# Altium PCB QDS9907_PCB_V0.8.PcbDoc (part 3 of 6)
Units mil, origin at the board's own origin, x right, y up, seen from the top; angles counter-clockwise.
Board outline 3410.03 x 4010.03 mil, 8 copper layers (Top Layer, GND1, INT1, INT2, PWR1, GND2, GND3, Bottom Layer), stack 81.668 mil thick; 250 components, 129 nets, 7010 pads, 701 vias.
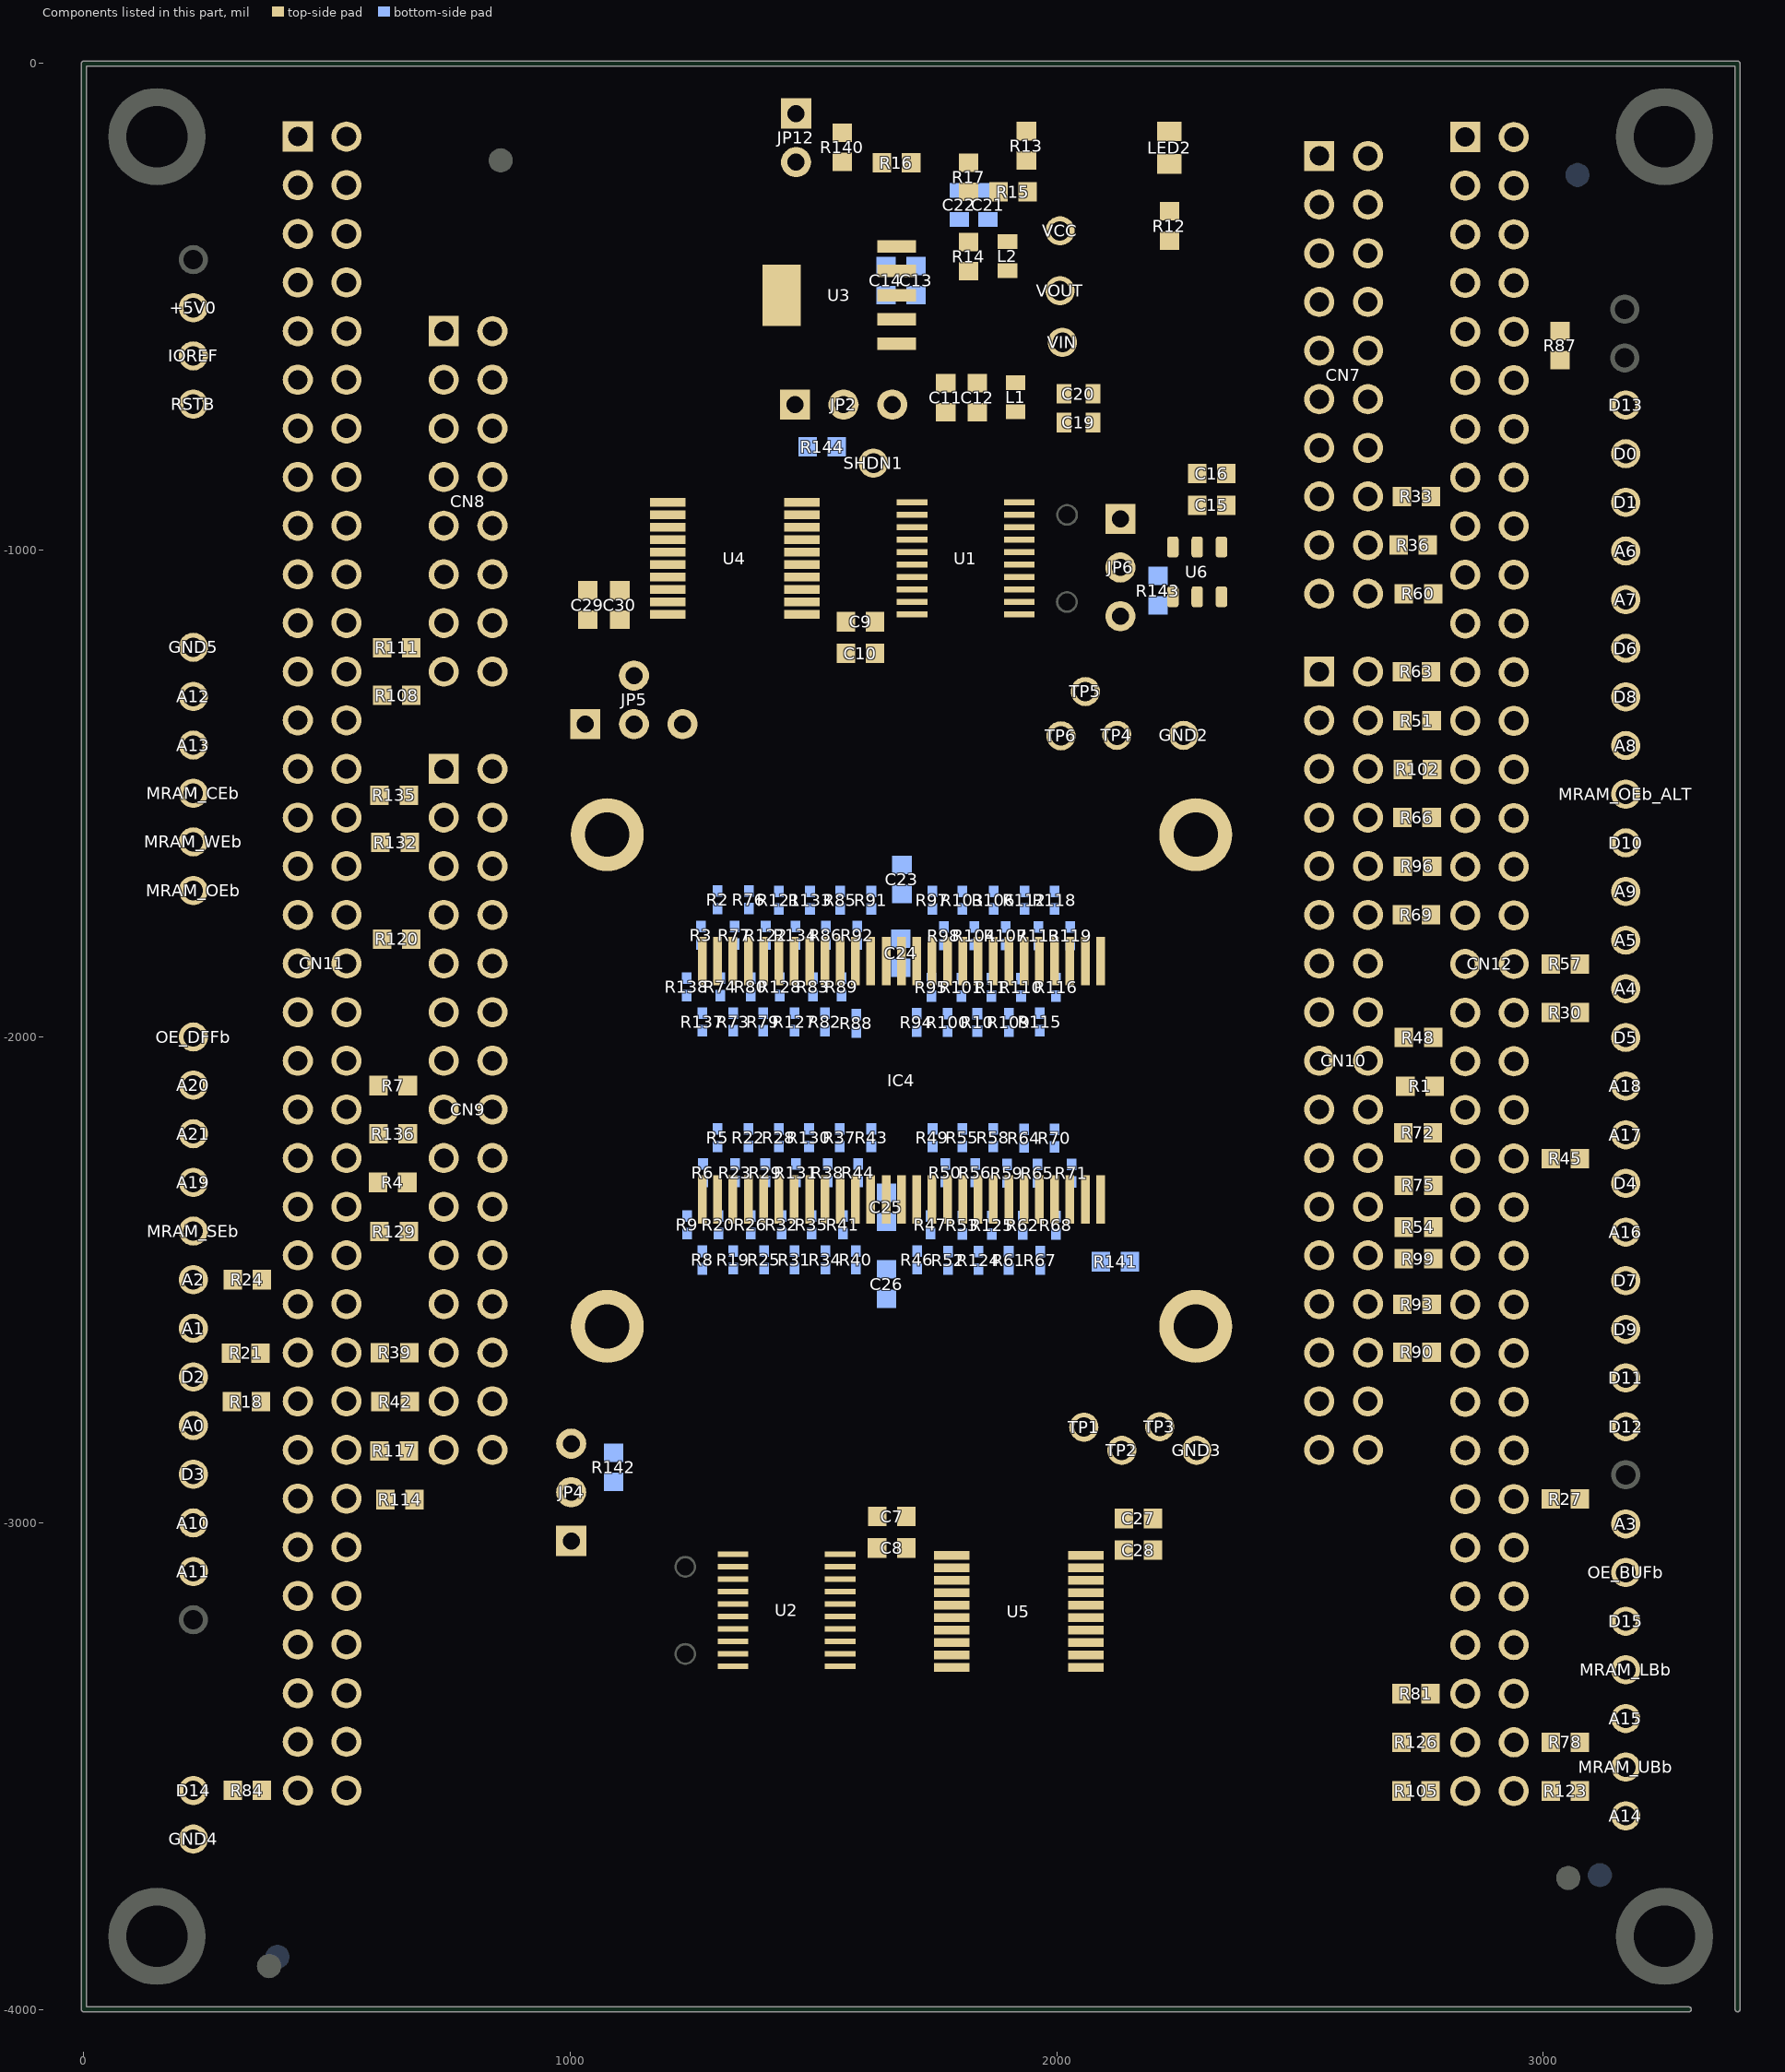
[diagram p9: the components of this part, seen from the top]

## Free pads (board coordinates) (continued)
  round 1.54 on Bottom Overlay: ""(1469.48,-3788.44) ""(1469.57,-3794.27) ""(1469.57,-3794.27) ""(1469.57,-3794.27) ""(1469.57,-3794.27) ""(1469.85,-3797.55) ""(1469.85,-3797.55) ""(1469.85,-3797.55) ""(1469.85,-3797.55) ""(1469.99,-3768.89) ""(1469.99,-3768.89) ""(1469.99,-3768.89) ""(1469.99,-3768.89) ""(1470.3,-3787.9) ""(1470.3,-3787.9) ""(1470.3,-3787.9) ""(1470.3,-3787.9) ""(1470.58,-3795.09) ""(1470.58,-3795.09) ""(1470.58,-3795.09) ""(1470.58,-3795.09) ""(1470.67,-3771.14) ""(1470.67,-3771.14) ""(1470.67,-3771.14) ""(1470.67,-3771.14) ""(1471.21,-3768.56) ""(1471.21,-3768.56) ""(1471.21,-3768.56) ""(1471.21,-3768.56) ""(1471.49,-3770.86) ""(1471.49,-3770.86) ""(1471.49,-3770.86) ""(1471.49,-3770.86) ""(1471.58,-3779.24) ""(1471.58,-3779.24) ""(1471.58,-3779.24) ""(1471.58,-3779.24) ""(1471.67,-3786.99) ""(1471.67,-3786.99) ""(1471.67,-3786.99) ""(1471.67,-3786.99) ""(1471.85,-3795.46) ""(1471.85,-3795.46) ""(1471.85,-3795.46) ""(1471.85,-3795.46) ""(1472.58,-3797.91) ""(1472.58,-3797.91) ""(1472.58,-3797.91) ""(1472.58,-3797.91) ""(1473.22,-3770.5) ""(1473.22,-3770.5) ""(1473.22,-3770.5) ""(1473.22,-3770.5) ""(1473.31,-3795.73) ""(1473.31,-3795.73) ""(1473.31,-3795.73) ""(1473.31,-3795.73) ""(1473.4,-3786.44) ""(1473.4,-3786.44) ""(1473.4,-3786.44) ""(1473.4,-3786.44) ""(1473.95,-3778.06) ""(1473.95,-3778.06) ""(1473.95,-3778.06) ""(1473.95,-3778.06) ""(1474.33,-3795.67) ""(1474.33,-3795.67) ""(1474.33,-3795.67) ""(1474.33,-3795.67) ""(1474.4,-3768.28) ""(1474.4,-3768.28) ""(1474.4,-3768.28) ""(1474.4,-3768.28) ""(1474.5,-3798.01) ""(1474.5,-3798.01) ""(1474.5,-3798.01) ""(1474.5,-3798.01) ""(1474.77,-3770.77) ""(1474.77,-3770.77) ""(1474.77,-3770.77) ""(1474.77,-3770.77) ""(1475.14,-3795.56) ""(1475.14,-3795.56) ""(1475.14,-3795.56) ""(1475.14,-3795.56) ""(1475.33,-3797.89) ""(1475.33,-3797.89) ""(1475.33,-3797.89) ""(1475.33,-3797.89) ""(1475.68,-3777.15) ""(1475.68,-3777.15) ""(1475.68,-3777.15) ""(1475.68,-3777.15) ""(1475.77,-3785.25) ""(1475.77,-3785.25) ""(1475.77,-3785.25) ""(1475.77,-3785.25) ""(1475.85,-3768.48) ""(1475.85,-3768.48) ""(1475.85,-3768.48) ""(1475.85,-3768.48) ""(1475.96,-3771.23) ""(1475.96,-3771.23) ""(1475.96,-3771.23) ""(1475.96,-3771.23) ""(1475.96,-3797.8) ""(1475.96,-3797.8) ""(1475.96,-3797.8) ""(1475.96,-3797.8) ""(1476.03,-3795.43) ""(1476.03,-3795.43) ""(1476.03,-3795.43) ""(1476.03,-3795.43) ""(1476.69,-3776.15) ""(1476.69,-3776.15) ""(1476.69,-3776.15) ""(1476.69,-3776.15) ""(1476.7,-3795.28) ""(1476.7,-3795.28) ""(1476.7,-3795.28) ""(1476.7,-3795.28) ""(1476.78,-3772.41) ""(1476.78,-3772.41) ""(1476.78,-3772.41) ""(1476.78,-3772.41) ""(1476.83,-3797.65) ""(1476.83,-3797.65) ""(1476.83,-3797.65) ""(1476.83,-3797.65) ""(1477.23,-3768.89) ""(1477.23,-3768.89) ""(1477.23,-3768.89) ""(1477.23,-3768.89) ""(1477.23,-3774.87) ""(1477.23,-3774.87) ""(1477.23,-3774.87) ""(1477.23,-3774.87) ""(1477.23,-3773.78) ""(1477.23,-3773.78) ""(1477.23,-3773.78) ""(1477.23,-3773.78) ""(1477.33,-3797.56) ""(1477.33,-3797.56) ""(1477.33,-3797.56) ""(1477.33,-3797.56) ""(1477.51,-3784.62) ""(1477.51,-3784.62) ""(1477.51,-3784.62) ""(1477.51,-3784.62) ""(1477.87,-3797.37) ""(1477.87,-3797.37) ""(1477.87,-3797.37) ""(1477.87,-3797.37) ""(1478.01,-3794.58) ""(1478.01,-3794.58) ""(1478.01,-3794.58) ""(1478.01,-3794.58) ""(1478.44,-3794.21) ""(1478.44,-3794.21) ""(1478.44,-3794.21) ""(1478.44,-3794.21) ""(1478.6,-3769.58) ""(1478.6,-3769.58) ""(1478.6,-3769.58) ""(1478.6,-3769.58) ""(1478.96,-3793.73) ""(1478.96,-3793.73) ""(1478.96,-3793.73) ""(1478.96,-3793.73) ""(1479.15,-3796.64) ""(1479.15,-3796.64) ""(1479.15,-3796.64) ""(1479.15,-3796.64) ""(1479.33,-3783.34) ""(1479.33,-3783.34) ""(1479.33,-3783.34) ""(1479.33,-3783.34) ""(1479.53,-3796.39) ""(1479.53,-3796.39) ""(1479.53,-3796.39) ""(1479.53,-3796.39) ""(1479.6,-3792.72) ""(1479.6,-3792.72) ""(1479.79,-3796.28) ""(1479.79,-3796.28) ""(1479.79,-3796.28) ""(1479.79,-3796.28) ""(1480.05,-3796.28) ""(1480.05,-3796.28) ""(1480.05,-3796.28) ""(1480.05,-3796.28) ""(1480.06,-3770.59) ""(1480.06,-3770.59) ""(1480.06,-3770.59) ""(1480.06,-3770.59) ""(1480.33,-3791.36) ""(1480.33,-3791.36) ""(1480.33,-3791.36) ""(1480.33,-3791.36) ""(1480.36,-3796.34) ""(1480.36,-3796.34) ""(1480.36,-3796.34) ""(1480.36,-3796.34) ""(1480.44,-3796.37) ""(1480.44,-3796.37) ""(1480.57,-3790.47) ""(1480.57,-3790.47) ""(1480.57,-3790.47) ""(1480.58,-3790.47) ""(1480.58,-3790.47) ""(1480.79,-3782.25) ""(1480.79,-3782.25) ""(1480.79,-3782.25) ""(1480.79,-3782.25) ""(1480.87,-3796.75) ""(1480.87,-3796.75) ""(1480.87,-3796.75) ""(1480.87,-3796.75) ""(1481.32,-3789.9) ""(1481.32,-3789.9) ""(1481.32,-3789.9) ""(1481.32,-3789.9) ""(1481.32,-3789.9) ""(1481.48,-3797.16) ""(1481.48,-3797.16) ""(1481.48,-3797.16) ""(1481.52,-3772.05) ""(1481.52,-3772.05) ""(1481.52,-3772.05) ""(1481.52,-3772.05) ""(1481.7,-3797.19) ""(1481.7,-3797.19) ""(1481.7,-3797.19) ""(1481.7,-3797.19) ""(1481.7,-3789.9) ""(1481.7,-3789.9) ""(1481.7,-3789.9) ""(1481.7,-3789.9) ""(1481.97,-3781.06) ""(1481.97,-3781.06) ""(1481.97,-3781.06) ""(1481.97,-3781.06) ""(1482.34,-3773.41) ""(1482.34,-3773.41) ""(1482.34,-3773.41) ""(1482.34,-3773.41) ""(1482.79,-3779.61) ""(1482.79,-3779.61) ""(1482.79,-3779.61) ""(1482.79,-3779.61) ""(1482.98,-3777.06) ""(1482.98,-3777.06) ""(1482.98,-3775.23) ""(1482.98,-3775.23) ""(1482.98,-3777.06) ""(1482.98,-3777.06) ""(1482.98,-3775.23) ""(1482.98,-3775.23) ""(1483.25,-3796.42) ""(1483.25,-3796.42) ""(1483.25,-3796.42) ""(1483.25,-3790.67) ""(1483.25,-3790.67) ""(1483.25,-3790.67) ""(1483.25,-3796.42) ""(1483.25,-3796.42) ""(1483.25,-3790.67) ""(1483.25,-3790.67) ""(1493.57,-3796.37) ""(1493.57,-3796.37) ""(1493.57,-3796.37) ""(1493.57,-3796.37) ""(1493.57,-3796.07) ""(1493.57,-3796.07) ""(1493.57,-3796.07) ""(1493.57,-3796.07) ""(1494.1,-3795.33) ""(1494.1,-3795.33) ""(1494.1,-3795.33) ""(1494.1,-3795.33) ""(1494.34,-3797.14) ""(1494.34,-3797.14) ""(1494.34,-3797.14) ""(1494.34,-3797.14) ""(1494.54,-3795.19) ""(1494.54,-3795.19) ""(1494.54,-3795.19) ""(1494.54,-3795.19) ""(1495.13,-3795.06) ""(1495.13,-3795.06) ""(1495.13,-3795.06) ""(1495.13,-3795.06) ""(1495.43,-3794.76) ""(1495.43,-3794.76) ""(1495.43,-3794.76) ""(1495.43,-3794.76) ""(1495.64,-3794.51) ""(1495.64,-3794.51) ""(1495.64,-3794.51) ""(1495.64,-3794.51) ""(1495.89,-3794.04) ""(1495.89,-3794.04) ""(1495.89,-3794.04) ""(1495.89,-3794.04) ""(1496.02,-3793.54) ""(1496.02,-3793.54) ""(1496.02,-3793.54) ""(1496.02,-3793.54) ""(1496.02,-3781.4) ""(1496.02,-3781.4) ""(1496.02,-3781.4) ""(1496.02,-3781.4) ""(1496.04,-3780.85) ""(1496.04,-3780.85) ""(1496.04,-3780.85) ""(1496.04,-3780.85) ""(1496.15,-3780.46) ""(1496.15,-3780.46) ""(1496.15,-3780.46) ""(1496.15,-3780.46) ""(1496.59,-3779.39) ""(1496.59,-3779.39) ""(1496.59,-3779.39) ""(1496.59,-3779.39) ""(1497.05,-3778.59) ""(1497.05,-3778.59) ""(1497.05,-3778.59) ""(1497.05,-3778.59) ""(1497.49,-3778.12) ""(1497.49,-3778.12) ""(1497.49,-3778.12) ""(1497.49,-3778.12) ""(1498.67,-3777.46) ""(1498.67,-3777.46) ""(1498.67,-3777.46) ""(1498.67,-3777.46) ""(1500.31,-3776.96) ""(1500.31,-3776.96) ""(1500.32,-3776.96) ""(1500.32,-3776.96) ""(1501.96,-3776.96) ""(1501.96,-3776.96) ""(1501.96,-3776.96) ""(1501.96,-3776.96) ""(1502,-3793.83) ""(1502,-3793.83) ""(1502.04,-3794.38) ""(1502.04,-3794.38) ""(1502.04,-3782.23) ""(1502.04,-3782.23) ""(1502.04,-3794.38) ""(1502.04,-3794.38) ""(1502.04,-3782.23) ""(1502.04,-3782.23) ""(1502.21,-3794.64) ""(1502.21,-3794.64) ""(1502.21,-3794.64) ""(1502.21,-3794.64) ""(1502.21,-3781.72) ""(1502.21,-3781.72) ""(1502.21,-3781.72) ""(1502.21,-3781.72) ""(1502.25,-3797.14) ""(1502.25,-3797.14) ""(1502.25,-3797.14) ""(1502.25,-3797.14) ""(1502.42,-3781.38) ""(1502.42,-3781.38) ""(1502.42,-3781.38) ""(1502.42,-3781.38) ""(1502.51,-3794.98) ""(1502.51,-3794.98) ""(1502.51,-3794.98) ""(1502.51,-3794.98) ""(1502.68,-3795.06) ""(1502.68,-3795.06) ""(1502.68,-3795.06) ""(1502.68,-3795.06) ""(1502.76,-3780.87) ""(1502.76,-3780.87) ""(1502.76,-3780.87) ""(1502.76,-3780.87) ""(1503.21,-3797.14) ""(1503.21,-3797.14) ""(1503.21,-3797.14) ""(1503.21,-3797.14) ""(1503.21,-3795.06) ""(1503.21,-3795.06) ""(1503.21,-3795.06) ""(1503.21,-3795.06) ""(1503.31,-3780.49) ""(1503.31,-3780.49) ""(1503.31,-3780.49) ""(1503.31,-3780.49) ""(1503.91,-3777.19) ""(1503.91,-3777.19) ""(1503.91,-3777.19) ""(1503.91,-3777.19) ""(1503.95,-3780.15) ""(1503.95,-3780.15) ""(1503.95,-3780.15) ""(1503.95,-3780.15) ""(1503.98,-3796.37) ""(1503.98,-3796.37) ""(1503.98,-3796.37) ""(1503.98,-3796.37) ""(1503.98,-3795.83) ""(1503.98,-3795.83) ""(1503.98,-3795.83) ""(1503.98,-3795.83) ""(1504.55,-3777.28) ""(1504.55,-3777.28) ""(1504.55,-3777.28) ""(1504.55,-3777.28) ""(1504.76,-3779.97) ""(1504.76,-3779.97) ""(1504.76,-3779.97) ""(1504.76,-3779.97) ""(1505.24,-3780.02) ""(1505.24,-3780.02) ""(1505.24,-3780.02) ""(1505.24,-3780.02) ""(1505.34,-3777.5) ""(1505.34,-3777.5) ""(1505.34,-3777.5) ""(1505.34,-3777.5) ""(1505.52,-3796.41) ""(1505.52,-3796.41) ""(1505.52,-3796.41) ""(1505.52,-3796.41) ""(1505.52,-3796.02) ""(1505.52,-3796.02) ""(1505.52,-3796.02) ""(1505.52,-3796.02) ""(1505.54,-3780.06) ""(1505.54,-3780.06) ""(1505.54,-3780.06) ""(1505.54,-3780.06) ""(1505.88,-3780.2) ""(1505.88,-3780.2) ""(1505.88,-3780.2) ""(1505.88,-3780.2) ""(1505.98,-3777.81) ""(1505.98,-3777.81) ""(1505.98,-3777.81) ""(1505.98,-3777.81) ""(1506.13,-3780.37) ""(1506.13,-3780.37) ""(1506.13,-3780.37) ""(1506.13,-3780.37) ""(1506.21,-3795.25) ""(1506.21,-3795.25) ""(1506.21,-3795.25) ""(1506.21,-3795.25) ""(1506.29,-3797.18) ""(1506.41,-3780.56) ""(1506.41,-3780.56) ""(1506.41,-3780.56) ""(1506.41,-3780.56) ""(1506.56,-3778.19) ""(1506.56,-3778.19) ""(1506.56,-3778.19) ""(1506.56,-3778.19) ""(1506.68,-3780.62) ""(1506.68,-3780.62) ""(1506.68,-3780.62) ""(1506.68,-3780.62) ""(1506.83,-3795.19) ""(1506.83,-3795.19) ""(1506.83,-3795.19) ""(1506.83,-3795.19) ""(1506.94,-3780.54) ""(1506.94,-3780.54) ""(1506.94,-3780.54) ""(1506.94,-3780.54) ""(1507.04,-3778.52) ""(1507.04,-3778.52) ""(1507.04,-3778.52) ""(1507.04,-3778.52) ""(1507.21,-3795.1) ""(1507.21,-3795.1) ""(1507.21,-3795.1) ""(1507.21,-3795.1) ""(1507.3,-3778.87) ""(1507.3,-3778.87) ""(1507.3,-3778.87) ""(1507.3,-3778.87) ""(1507.33,-3780.58) ""(1507.33,-3780.58) ""(1507.33,-3780.58) ""(1507.33,-3780.58) ""(1507.42,-3794.89) ""(1507.42,-3794.89) ""(1507.42,-3794.89) ""(1507.42,-3794.89) ""(1507.55,-3779.26) ""(1507.55,-3779.26) ""(1507.55,-3779.26) ""(1507.55,-3779.26) ""(1507.58,-3780.79) ""(1507.58,-3780.79) ""(1507.58,-3780.79) ""(1507.58,-3780.79) ""(1507.63,-3779.33) ""(1507.63,-3779.33) ""(1507.63,-3779.33) ""(1507.63,-3779.33) ""(1507.68,-3794.6) ""(1507.68,-3794.6) ""(1507.68,-3794.6) ""(1507.68,-3794.6) ""(1507.79,-3781.11) ""(1507.79,-3781.11) ""(1507.79,-3781.11) ""(1507.79,-3781.11) ""(1507.8,-3779.42) ""(1507.8,-3779.42) ""(1507.8,-3779.42) ""(1507.8,-3779.42) ""(1507.81,-3794.17) ""(1507.81,-3794.17) ""(1507.81,-3794.17) ""(1507.81,-3794.17) ""(1507.89,-3793.62) ""(1507.89,-3793.62) ""(1507.89,-3782.74) ""(1507.89,-3782.74) ""(1507.89,-3781.42) ""(1507.89,-3781.42) ""(1507.89,-3793.62) ""(1507.89,-3793.62) ""(1507.89,-3782.74) ""(1507.89,-3782.74) ""(1507.89,-3781.42) ""(1507.89,-3781.42) ""(1507.92,-3779.47) ""(1507.92,-3779.47) ""(1507.92,-3779.47) ""(1507.92,-3779.47) ""(1508.03,-3779.48) ""(1508.03,-3779.48) ""(1508.03,-3779.48) ""(1508.03,-3779.48) ""(1508.15,-3779.46) ""(1508.15,-3779.46) ""(1508.15,-3779.46) ""(1508.15,-3779.46) ""(1508.26,-3779.27) ""(1508.26,-3779.27) ""(1508.26,-3779.27) ""(1508.26,-3779.27) ""(1508.28,-3779.18) ""(1508.28,-3779.18) ""(1508.28,-3779.18) ""(1508.28,-3779.18) ""(1508.28,-3778.38) ""(1508.28,-3778.38) ""(1508.28,-3778.38) ""(1508.28,-3778.38) ""(1509.05,-3777.61) ""(1509.05,-3777.61) ""(1509.05,-3777.61) ""(1509.05,-3777.61) ""(1514.04,-3793.11) ""(1514.04,-3793.11) ""(1514.04,-3793.11) ""(1514.04,-3793.11) ""(1514.04,-3781.34) ""(1514.04,-3781.34) ""(1514.04,-3781.34) ""(1514.04,-3781.34) ""(1514.12,-3780.91) ""(1514.12,-3780.91) ""(1514.16,-3794.09) ""(1514.16,-3794.09) ""(1514.33,-3794.43) ""(1514.33,-3794.43) ""(1514.33,-3794.43) ""(1514.33,-3794.43) ""(1514.38,-3780.53) ""(1514.38,-3780.53) ""(1514.38,-3780.53) ""(1514.38,-3780.53) ""(1514.72,-3794.76) ""(1514.72,-3794.76) ""(1514.72,-3794.76) ""(1514.72,-3794.76) ""(1514.76,-3780.24) ""(1514.76,-3780.24) ""(1514.76,-3780.24) ""(1514.76,-3780.24) ""(1515.14,-3780.07) ""(1515.14,-3780.07) ""(1515.14,-3780.07) ""(1515.14,-3780.07) ""(1515.18,-3795.1) ""(1515.18,-3795.1) ""(1515.18,-3795.1) ""(1515.18,-3795.1) ""(1515.43,-3797.18) ""(1515.43,-3797.18) ""(1515.43,-3797.18) ""(1515.43,-3797.18) ""(1515.65,-3779.98) ""(1515.65,-3779.98) ""(1515.65,-3779.98) ""(1515.65,-3779.98) ""(1515.69,-3795.29) ""(1515.69,-3795.29) ""(1515.69,-3795.29) ""(1515.69,-3795.29) ""(1515.99,-3779.9) ""(1515.99,-3779.9) ""(1515.99,-3779.9) ""(1515.99,-3779.9) ""(1516.11,-3777.7) ""(1516.11,-3777.7) ""(1516.11,-3777.7) ""(1516.11,-3777.7) ""(1516.16,-3779.73) ""(1516.16,-3779.73) ""(1516.16,-3779.73) ""(1516.16,-3779.73) ""(1516.2,-3796.41) ""(1516.2,-3796.41) ""(1516.2,-3796.41) ""(1516.2,-3796.41) ""(1516.2,-3796.01) ""(1516.2,-3796.01) ""(1516.2,-3796.01) ""(1516.2,-3796.01) ""(1516.24,-3779.39) ""(1516.24,-3779.39) ""(1516.24,-3779.39) ""(1516.24,-3779.39) ""(1516.24,-3777.95) ""(1516.24,-3777.95) ""(1516.24,-3777.95) ""(1516.24,-3777.95) ""(1519.62,-3777.67) ""(1519.62,-3777.67) ""(1519.62,-3777.67) ""(1519.62,-3777.67) ""(1519.76,-3775.94) ""(1519.76,-3775.94) ""(1519.76,-3775.94) ""(1519.76,-3775.94) ""(1520.03,-3798.98) ""(1520.03,-3798.98) ""(1520.03,-3775.45) ""(1520.03,-3775.45) ""(1520.03,-3798.98) ""(1520.03,-3798.98) ""(1520.03,-3775.45) ""(1520.03,-3775.45) ""(1520.17,-3800.36) ""(1520.17,-3800.36) ""(1520.17,-3800.36) ""(1520.17,-3800.36) ""(1520.24,-3778.98) ""(1520.24,-3778.98) ""(1520.24,-3778.98) ""(1520.24,-3778.98) ""(1520.38,-3797.25) ""(1520.38,-3797.25) ""(1520.38,-3797.25) ""(1520.38,-3797.25) ""(1520.59,-3779.19) ""(1520.59,-3779.19) ""(1520.59,-3779.19) ""(1520.59,-3779.19) ""(1520.66,-3774.9) ""(1520.66,-3774.9) ""(1520.66,-3774.9) ""(1520.66,-3774.9) ""(1520.73,-3801.88) ""(1520.73,-3801.88) ""(1520.73,-3801.88) ""(1520.73,-3801.88) ""(1520.93,-3796.35) ""(1520.93,-3796.35) ""(1520.93,-3796.35) ""(1520.93,-3796.35) ""(1521.21,-3779.33) ""(1521.21,-3779.33) ""(1521.21,-3774.49) ""(1521.21,-3774.49) ""(1521.21,-3779.33) ""(1521.21,-3779.33) ""(1521.21,-3774.49) ""(1521.21,-3774.49) ""(1521.42,-3785.21) ""(1521.42,-3785.21) ""(1521.42,-3785.21) ""(1521.42,-3785.21) ""(1521.56,-3783.62) ""(1521.56,-3783.62) ""(1521.56,-3783.62) ""(1521.56,-3783.62) ""(1521.63,-3786.8) ""(1521.63,-3786.8) ""(1521.63,-3786.8) ""(1521.63,-3786.8) ""(1521.76,-3782.23) ""(1521.76,-3782.23) ""(1521.76,-3782.23) ""(1521.76,-3782.23) ""(1521.9,-3779.33) ""(1521.9,-3779.33) ""(1521.9,-3779.33) ""(1521.9,-3779.33) ""(1521.9,-3774.21) ""(1521.9,-3774.21) ""(1521.9,-3774.21) ""(1521.9,-3774.21) ""(1521.97,-3803.4) ""(1521.97,-3803.4) ""(1521.97,-3803.4) ""(1521.97,-3803.4) ""(1522.25,-3795.1) ""(1522.25,-3795.1) ""(1522.25,-3795.1) ""(1522.25,-3795.1) ""(1522.25,-3788.46) ""(1522.25,-3788.46) ""(1522.25,-3788.46) ""(1522.25,-3788.46) ""(1522.39,-3779.33) ""(1522.39,-3779.33) ""(1522.39,-3779.33) ""(1522.39,-3779.33) ""(1522.46,-3780.99) ""(1522.46,-3780.99) ""(1522.46,-3780.99) ""(1522.46,-3780.99) ""(1522.73,-3779.12) ""(1522.73,-3779.12) ""(1522.73,-3779.12) ""(1522.73,-3779.12) ""(1522.87,-3778.64) ""(1522.87,-3778.64) ""(1522.87,-3778.64) ""(1522.87,-3778.64) ""(1522.87,-3778.36) ""(1522.87,-3778.36) ""(1522.87,-3778.36) ""(1522.87,-3778.36) ""(1522.94,-3789.29) ""(1522.94,-3789.29) ""(1522.94,-3778.08) ""(1522.94,-3778.08) ""(1522.94,-3789.29) ""(1522.94,-3789.29) ""(1522.94,-3778.08) ""(1522.94,-3778.08) ""(1523.08,-3780.23) ""(1523.08,-3780.23) ""(1523.08,-3780.23) ""(1523.08,-3780.23) ""(1523.08,-3774.28) ""(1523.08,-3774.28) ""(1523.08,-3774.28) ""(1523.08,-3774.28) ""(1523.36,-3777.74) ""(1523.36,-3777.74) ""(1523.36,-3777.74) ""(1523.36,-3777.74) ""(1523.7,-3794.27) ""(1523.7,-3794.27) ""(1523.7,-3794.27) ""(1523.7,-3794.27) ""(1523.77,-3804.79) ""(1523.77,-3804.79) ""(1523.77,-3804.79) ""(1523.77,-3804.79) ""(1523.77,-3777.74) ""(1523.77,-3777.74) ""(1523.77,-3777.74) ""(1523.77,-3777.74) ""(1523.77,-3774.49) ""(1523.77,-3774.49) ""(1523.77,-3774.49) ""(1523.77,-3774.49) ""(1524.05,-3779.54) ""(1524.05,-3779.54) ""(1524.05,-3779.54) ""(1524.05,-3779.54) ""(1524.05,-3778.01) ""(1524.05,-3778.01) ""(1524.05,-3778.01) ""(1524.05,-3778.01) ""(1524.33,-3774.9) ""(1524.33,-3774.9) ""(1524.33,-3774.9) ""(1524.33,-3774.9) ""(1524.4,-3790.6) ""(1524.4,-3790.6) ""(1524.4,-3790.6) ""(1524.4,-3790.6) ""(1524.88,-3793.79) ""(1524.88,-3793.79) ""(1524.88,-3793.79) ""(1524.88,-3793.79) ""(1524.88,-3775.45) ""(1524.88,-3775.45) ""(1524.88,-3775.45) ""(1524.88,-3775.45) ""(1525.23,-3777.74) ""(1525.23,-3777.74) ""(1525.23,-3777.74) ""(1525.23,-3777.74) ""(1525.23,-3777.18) ""(1525.23,-3777.18) ""(1525.23,-3777.18) ""(1525.23,-3777.18) ""(1525.23,-3776.28) ""(1525.23,-3776.28) ""(1525.23,-3776.28) ""(1525.23,-3776.28) ""(1525.37,-3778.01) ""(1525.37,-3778.01) ""(1525.37,-3778.01) ""(1525.37,-3778.01) ""(1525.43,-3805.62) ""(1525.43,-3805.62) ""(1525.44,-3805.62) ""(1525.44,-3805.62) ""(1525.71,-3801.33) ""(1525.71,-3801.33) ""(1525.71,-3778.15) ""(1525.71,-3778.15) ""(1525.71,-3801.33) ""(1525.71,-3801.33) ""(1525.71,-3778.15) ""(1525.71,-3778.15) ""(1525.78,-3800.71) ""(1525.78,-3800.71) ""(1525.78,-3800.71) ""(1525.78,-3800.71) ""(1525.85,-3791.5) ""(1525.85,-3791.5) ""(1525.85,-3791.5) ""(1525.85,-3791.5) ""(1525.92,-3800.15) ""(1525.92,-3800.15) ""(1525.92,-3800.15) ""(1525.92,-3800.15) ""(1525.99,-3801.81) ""(1525.99,-3801.81) ""(1525.99,-3801.81) ""(1525.99,-3801.81) ""(1526.2,-3799.81) ""(1526.2,-3799.81) ""(1526.2,-3799.81) ""(1526.2,-3799.81) ""(1526.4,-3777.8) ""(1526.4,-3777.8) ""(1526.4,-3777.8) ""(1526.4,-3777.8) ""(1526.54,-3802.37) ""(1526.54,-3802.37) ""(1526.54,-3802.37) ""(1526.54,-3802.37) ""(1526.75,-3799.39) ""(1526.75,-3799.39) ""(1527.17,-3802.85) ""(1527.17,-3802.85) ""(1527.17,-3802.85) ""(1527.17,-3802.85) ""(1527.3,-3793.51) ""(1527.3,-3793.51) ""(1527.3,-3793.51) ""(1527.3,-3793.51) ""(1527.44,-3776.98) ""(1527.44,-3776.98) ""(1527.44,-3776.98) ""(1527.44,-3776.98) ""(1527.79,-3791.85) ""(1527.79,-3791.85) ""(1527.79,-3791.85) ""(1527.79,-3791.85) ""(1527.86,-3787.21) ""(1527.86,-3787.21) ""(1527.86,-3787.21) ""(1527.86,-3787.21) ""(1527.86,-3782.23) ""(1527.86,-3782.23) ""(1527.86,-3782.23) ""(1527.86,-3782.23) ""(1527.87,-3781.29) ""(1527.87,-3781.29) ""(1527.87,-3781.29) ""(1527.87,-3781.29) ""(1527.93,-3806.03) ""(1527.93,-3806.03) ""(1527.93,-3776.84) ""(1527.93,-3776.84) ""(1527.93,-3806.03) ""(1527.93,-3806.03) ""(1527.93,-3776.84) ""(1527.93,-3776.84) ""(1528,-3803.27) ""(1528,-3803.27) ""(1528,-3803.27) ""(1528,-3803.27) ""(1528.04,-3780.57) ""(1528.04,-3780.57) ""(1528.04,-3780.57) ""(1528.04,-3780.57) ""(1528.06,-3788.29) ""(1528.06,-3788.29) ""(1528.06,-3788.29) ""(1528.06,-3788.29) ""(1528.07,-3798.56) ""(1528.07,-3798.56) ""(1528.07,-3798.56) ""(1528.07,-3798.56) ""(1528.28,-3788.84) ""(1528.28,-3788.84) ""(1528.28,-3788.84) ""(1528.28,-3788.84) ""(1528.36,-3779.79) ""(1528.36,-3779.79) ""(1528.36,-3779.79) ""(1528.36,-3779.79) ""(1528.64,-3789.33) ""(1528.64,-3789.33) ""(1528.64,-3789.33) ""(1528.64,-3789.33) ""(1528.76,-3779.34) ""(1528.76,-3779.34) ""(1528.76,-3779.34) ""(1528.76,-3779.34) ""(1528.91,-3789.6) ""(1528.91,-3789.6) ""(1528.91,-3789.6) ""(1528.91,-3789.6) ""(1529.04,-3803.61) ""(1529.04,-3803.61) ""(1529.04,-3803.61) ""(1529.04,-3803.61) ""(1529.17,-3798.28) ""(1529.17,-3798.28) ""(1529.17,-3798.28) ""(1529.17,-3798.28) ""(1529.24,-3776.42) ""(1529.24,-3776.42) ""(1529.24,-3776.42) ""(1529.24,-3776.42) ""(1529.31,-3789.86) ""(1529.31,-3789.86) ""(1529.31,-3789.86) ""(1529.31,-3789.86) ""(1529.33,-3779.03) ""(1529.33,-3779.03) ""(1529.33,-3779.03) ""(1529.33,-3779.03) ""(1529.38,-3792.13) ""(1529.38,-3792.13) ""(1529.38,-3792.13) ""(1529.38,-3792.13) ""(1529.99,-3778.88) ""(1529.99,-3778.88) ""(1529.99,-3778.88) ""(1529.99,-3778.88) ""(1530.07,-3803.89) ""(1530.07,-3803.89) ""(1530.07,-3803.89) ""(1530.07,-3803.89) ""(1530.14,-3806.17) ""(1530.14,-3806.17) ""(1530.14,-3806.17) ""(1530.14,-3806.17) ""(1530.28,-3798.15) ""(1530.28,-3798.15) ""(1530.28,-3793.51) ""(1530.28,-3793.51) ""(1530.28,-3798.15) ""(1530.28,-3798.15) ""(1530.28,-3793.51) ""(1530.28,-3793.51) ""(1530.42,-3790.05) ""(1530.42,-3790.05) ""(1530.42,-3790.05) ""(1530.42,-3790.05) ""(1530.48,-3778.88) ""(1530.48,-3778.88) ""(1530.48,-3778.88) ""(1530.48,-3778.88) ""(1531.04,-3792.06) ""(1531.04,-3792.06) ""(1531.04,-3792.06) ""(1531.04,-3792.06) ""(1531.04,-3776.42) ""(1531.04,-3776.42) ""(1531.04,-3776.42) ""(1531.04,-3776.42) ""(1531.05,-3779.03) ""(1531.05,-3779.03) ""(1531.05,-3779.03) ""(1531.05,-3779.03) ""(1531.11,-3804.17) ""(1531.11,-3804.17) ""(1531.11,-3798.08) ""(1531.11,-3798.08) ""(1531.11,-3804.17) ""(1531.11,-3804.17) ""(1531.11,-3798.08) ""(1531.11,-3798.08) ""(1531.18,-3789.84) ""(1531.18,-3789.84) ""(1531.18,-3789.84) ""(1531.18,-3789.84) ""(1531.65,-3779.26) ""(1531.65,-3779.26) ""(1531.65,-3779.26) ""(1531.65,-3779.26) ""(1531.74,-3789.36) ""(1531.74,-3789.36) ""(1531.74,-3789.36) ""(1531.74,-3789.36) ""(1532.05,-3779.49) ""(1532.05,-3779.49) ""(1532.05,-3779.49) ""(1532.05,-3779.49) ""(1532.08,-3793.72) ""(1532.08,-3793.72) ""(1532.08,-3793.72) ""(1532.08,-3793.72) ""(1532.15,-3788.94) ""(1532.15,-3788.94) ""(1532.15,-3788.94) ""(1532.15,-3788.94) ""(1532.22,-3798.15) ""(1532.22,-3798.15) ""(1532.22,-3798.15) ""(1532.22,-3798.15) ""(1532.36,-3804.23) ""(1532.36,-3804.23) ""(1532.36,-3804.23) ""(1532.36,-3804.23) ""(1532.37,-3779.89) ""(1532.37,-3779.89) ""(1532.37,-3779.89) ""(1532.37,-3779.89) ""(1532.57,-3791.92) ""(1532.57,-3791.92) ""(1532.57,-3791.92) ""(1532.57,-3791.92) ""(1532.57,-3788.25) ""(1532.57,-3788.25) ""(1532.57,-3788.25) ""(1532.57,-3788.25) ""(1532.62,-3780.36) ""(1532.62,-3780.36) ""(1532.62,-3780.36) ""(1532.62,-3780.36) ""(1532.64,-3805.9) ""(1532.64,-3805.9) ""(1532.64,-3805.9) ""(1532.64,-3805.9) ""(1532.71,-3780.76) ""(1532.71,-3780.76) ""(1532.71,-3780.76) ""(1532.71,-3780.76) ""(1532.71,-3787.49) ""(1532.71,-3787.49) ""(1532.71,-3781.33) ""(1532.71,-3781.33) ""(1532.71,-3787.49) ""(1532.71,-3787.49) ""(1532.71,-3781.33) ""(1532.71,-3781.33) ""(1533.33,-3803.89) ""(1533.33,-3803.89) ""(1533.33,-3803.89) ""(1533.33,-3803.89) ""(1533.33,-3793.93) ""(1533.33,-3793.93) ""(1533.33,-3793.93) ""(1533.33,-3793.93) ""(1533.33,-3791.71) ""(1533.33,-3791.71) ""(1533.33,-3791.71) ""(1533.33,-3791.71) ""(1533.47,-3776.56) ""(1533.47,-3776.56) ""(1533.47,-3776.56) ""(1533.47,-3776.56) ""(1533.54,-3801.61) ""(1533.54,-3801.61) ""(1533.54,-3801.61) ""(1533.54,-3801.61) ""(1533.54,-3800.78) ""(1533.54,-3800.78) ""(1533.54,-3800.78) ""(1533.54,-3800.78) ""(1533.74,-3803.54) ""(1533.74,-3803.54) ""(1533.74,-3801.95) ""(1533.74,-3801.95) ""(1533.74,-3800.36) ""(1533.74,-3800.36) ""(1533.74,-3798.35) ""(1533.74,-3798.35) ""(1533.74,-3791.92) ""(1533.74,-3791.92) ""(1533.74,-3803.54) ""(1533.74,-3803.54) ""(1533.74,-3801.95) ""(1533.74,-3801.95) ""(1533.74,-3800.36) ""(1533.74,-3800.36) ""(1533.74,-3798.35) ""(1533.74,-3798.35) ""(1533.74,-3791.92) ""(1533.74,-3791.92) ""(1533.95,-3803.27) ""(1533.95,-3803.27) ""(1533.95,-3803.27) ""(1533.95,-3803.27) ""(1533.95,-3802.57) ""(1533.95,-3802.57) ""(1533.95,-3802.57) ""(1533.95,-3802.57) ""(1534.02,-3800.01) ""(1534.02,-3800.01) ""(1534.02,-3800.01) ""(1534.02,-3800.01) ""(1534.09,-3802.85) ""(1534.09,-3802.85) ""(1534.09,-3802.85) ""(1534.09,-3802.85) ""(1534.44,-3777.11) ""(1534.44,-3777.11) ""(1534.44,-3777.11) ""(1534.44,-3777.11) ""(1534.51,-3794.2) ""(1534.51,-3794.2) ""(1534.51,-3794.2) ""(1534.51,-3794.2) ""(1534.64,-3799.53) ""(1534.64,-3799.53) ""(1534.64,-3799.53) ""(1534.64,-3799.53) ""(1534.78,-3805.62) ""(1534.78,-3805.62) ""(1534.78,-3805.62) ""(1534.78,-3805.62) ""(1534.99,-3798.56) ""(1534.99,-3798.56) ""(1534.99,-3798.56) ""(1534.99,-3798.56) ""(1534.99,-3794.41) ""(1534.99,-3794.41) ""(1534.99,-3794.41) ""(1534.99,-3794.41) ""(1535.27,-3794.34) ""(1535.27,-3794.34) ""(1535.27,-3794.34) ""(1535.27,-3794.34) ""(1535.27,-3793.86) ""(1535.27,-3793.86) ""(1535.27,-3793.86) ""(1535.27,-3793.86) ""(1535.34,-3799.32) ""(1535.34,-3799.32) ""(1535.34,-3799.32) ""(1535.34,-3799.32) ""(1535.41,-3794.13) ""(1535.41,-3794.13) ""(1535.41,-3794.13) ""(1535.41,-3794.13) ""(1535.82,-3798.77) ""(1535.82,-3798.77) ""(1535.82,-3798.77) ""(1535.82,-3798.77) ""(1535.82,-3791.02) ""(1535.82,-3791.02) ""(1535.82,-3791.02) ""(1535.82,-3791.02) ""(1535.89,-3799.25) ""(1535.89,-3799.25) ""(1535.89,-3799.25) ""(1535.89,-3799.25) ""(1535.96,-3791.37) ""(1535.96,-3791.37) ""(1535.96,-3791.37) ""(1535.96,-3791.37) ""(1535.96,-3777.87) ""(1535.96,-3777.87) ""(1535.96,-3777.87) ""(1535.96,-3777.87) ""(1536.03,-3790.67) ""(1536.03,-3790.67) ""(1536.03,-3790.67) ""(1536.03,-3790.67) ""(1536.1,-3805.34) ""(1536.1,-3805.34) ""(1536.1,-3805.34) ""(1536.1,-3805.34) ""(1536.31,-3790.33) ""(1536.31,-3790.33) ""(1536.31,-3790.33) ""(1536.31,-3790.33) ""(1536.72,-3799.39) ""(1536.72,-3799.39) ""(1536.72,-3799.39) ""(1536.72,-3799.39) ""(1536.79,-3798.91) ""(1536.79,-3798.91) ""(1537,-3778.91) ""(1537,-3778.91) ""(1537,-3778.91) ""(1537,-3778.91) ""(1537.14,-3789.64) ""(1537.14,-3789.64) ""(1537.14,-3789.64) ""(1537.14,-3789.64) ""(1537.41,-3804.58) ""(1537.41,-3804.58) ""(1537.41,-3804.58) ""(1537.41,-3804.58) ""(1537.48,-3799.74) ""(1537.48,-3799.74) ""(1537.48,-3799.74) ""(1537.48,-3799.74) ""(1537.69,-3799.05) ""(1537.69,-3799.05) ""(1537.69,-3799.05) ""(1537.69,-3799.05) ""(1537.83,-3788.67) ""(1537.83,-3788.67) ""(1537.83,-3788.67) ""(1537.83,-3788.67) ""(1538.04,-3803.96) ""(1538.04,-3803.96) ""(1538.04,-3780.16) ""(1538.04,-3780.16) ""(1538.04,-3803.96) ""(1538.04,-3803.96) ""(1538.04,-3780.16) ""(1538.04,-3780.16) ""(1538.18,-3800.08) ""(1538.18,-3800.08) ""(1538.18,-3800.08) ""(1538.18,-3800.08) ""(1538.31,-3787.91) ""(1538.31,-3787.91) ""(1538.31,-3787.91) ""(1538.31,-3787.91) ""(1538.59,-3803.47) ""(1538.59,-3803.47) ""(1538.59,-3803.47) ""(1538.59,-3803.47) ""(1538.73,-3799.32) ""(1538.73,-3799.32) ""(1538.73,-3799.32) ""(1538.73,-3799.32) ""(1538.73,-3787.08) ""(1538.73,-3787.08) ""(1538.73,-3787.08) ""(1538.73,-3787.08) ""(1538.73,-3781.26) ""(1538.73,-3781.26) ""(1538.73,-3781.26) ""(1538.73,-3781.26) ""(1538.87,-3800.57) ""(1538.87,-3800.57) ""(1538.87,-3800.57) ""(1538.87,-3800.57) ""(1538.94,-3802.57) ""(1538.94,-3802.57) ""(1538.94,-3802.57) ""(1538.94,-3802.57) ""(1539.08,-3801.61) ""(1539.08,-3801.61) ""(1539.08,-3801.12) ""(1539.08,-3801.12) ""(1539.08,-3785.76) ""(1539.08,-3785.76) ""(1539.08,-3801.61) ""(1539.08,-3801.61) ""(1539.08,-3801.12) ""(1539.08,-3801.12) ""(1539.08,-3785.76) ""(1539.08,-3785.76) ""(1539.15,-3782.65) ""(1539.15,-3782.65) ""(1539.15,-3782.65) ""(1539.15,-3782.65) ""(1539.21,-3799.25) ""(1539.21,-3799.25) ""(1539.21,-3799.25) ""(1539.21,-3799.25) ""(1539.21,-3784.17) ""(1539.21,-3784.17) ""(1539.21,-3784.17) ""(1539.21,-3784.17) ""(1539.84,-3798.98) ""(1539.84,-3798.98) ""(1539.84,-3798.98) ""(1539.84,-3798.98) ""(1540.05,-3796.69) ""(1540.05,-3796.69) ""(1540.05,-3796.69) ""(1540.05,-3796.69) ""(1540.12,-3798.7) ""(1540.12,-3798.7) ""(1540.12,-3798.7) ""(1540.12,-3798.7) ""(1540.32,-3798.01) ""(1540.32,-3798.01) ""(1540.32,-3798.01) ""(1540.32,-3798.01) ""(1540.32,-3797.52) ""(1540.32,-3797.52) ""(1540.32,-3797.52) ""(1540.32,-3797.52) ""(1544.12,-3796.81) ""(1544.12,-3796.81) ""(1544.12,-3796.81) ""(1544.12,-3796.81) ""(1544.12,-3794.81) ""(1544.12,-3794.81) ""(1544.12,-3794.81) ""(1544.12,-3794.81) ""(1544.23,-3794.81) ""(1544.23,-3794.81) ""(1544.23,-3794.81) ""(1544.23,-3794.81) ""(1544.61,-3794.71) ""(1544.61,-3794.71) ""(1544.61,-3794.71) ""(1544.61,-3794.71) ""(1545.04,-3794.55) ""(1545.04,-3794.55) ""(1545.04,-3794.55) ""(1545.05,-3794.55) ""(1545.54,-3793.82) ""(1545.54,-3793.82) ""(1545.54,-3793.82) ""(1545.54,-3793.82) ""(1545.54,-3793.22) ""(1545.54,-3793.22) ""(1545.54,-3793.22) ""(1545.54,-3793.22) ""(1545.54,-3777.66) ""(1545.54,-3777.66) ""(1545.54,-3777.66) ""(1545.55,-3777.66) ""(1546.32,-3776.89) ""(1546.32,-3776.89) ""(1546.32,-3776.89) ""(1546.32,-3776.89) ""(1551.92,-3793.42) ""(1551.92,-3793.42) ""(1551.92,-3793.42) ""(1551.92,-3793.42) ""(1551.92,-3780.56) ""(1551.92,-3780.56) ""(1551.92,-3780.56) ""(1551.92,-3780.56) ""(1551.97,-3780.22) ""(1551.97,-3780.22) ""(1551.97,-3780.22) ""(1551.97,-3780.22) ""(1552.05,-3793.98) ""(1552.05,-3793.98) ""(1552.05,-3793.98) ""(1552.05,-3793.98) ""(1552.16,-3780.01) ""(1552.16,-3780.01) ""(1552.16,-3780.01) ""(1552.16,-3780.01) ""(1552.33,-3794.32) ""(1552.33,-3794.32) ""(1552.33,-3794.32) ""(1552.33,-3794.32) ""(1552.38,-3779.77) ""(1552.38,-3779.77) ""(1552.38,-3779.77) ""(1552.38,-3779.77) ""(1552.58,-3779.61) ""(1552.58,-3779.61) ""(1552.58,-3779.61) ""(1552.58,-3779.61) ""(1552.77,-3779.46) ""(1552.77,-3779.46) ""(1552.77,-3779.46) ""(1552.77,-3779.46) ""(1552.82,-3794.67) ""(1552.82,-3794.67) ""(1552.82,-3794.67) ""(1552.82,-3794.67) ""(1553.01,-3779.37) ""(1553.01,-3779.37) ""(1553.01,-3779.37) ""(1553.01,-3779.37) ""(1553.29,-3776.89) ""(1553.29,-3796.81) ""(1553.29,-3796.81) ""(1553.29,-3796.81) ""(1553.29,-3796.81) ""(1553.29,-3779.37) ""(1553.29,-3779.37) ""(1553.29,-3779.37) ""(1553.29,-3779.37) ""(1553.29,-3776.89) ""(1553.29,-3776.89) ""(1553.29,-3776.89) ""(1553.52,-3794.88) ""(1553.52,-3794.88) ""(1553.52,-3794.88) ""(1553.52,-3794.88) ""(1554.06,-3796.04) ""(1554.06,-3796.04) ""(1554.06,-3796.04) ""(1554.06,-3796.04) ""(1554.06,-3795.62) ""(1554.06,-3795.62) ""(1554.06,-3795.62) ""(1554.06,-3795.62) ""(1554.06,-3778.59) ""(1554.06,-3778.59) ""(1554.06,-3778.59) ""(1554.06,-3778.59) ""(1554.06,-3777.66) ""(1554.06,-3777.66) ""(1554.06,-3777.66) ""(1554.06,-3777.66) ""(1555.97,-3791.31) ""(1555.97,-3791.31) ""(1555.97,-3791.31) ""(1555.97,-3791.31) ""(1556.1,-3789.49) ""(1556.1,-3789.49) ""(1556.1,-3789.49) ""(1556.1,-3789.49) ""(1556.49,-3788.06) ""(1556.49,-3788.06) ""(1556.49,-3788.06) ""(1556.49,-3788.06) ""(1556.88,-3793.39) ""(1556.88,-3793.39) ""(1556.88,-3793.39) ""(1556.88,-3793.39) ""(1557.29,-3781.38) ""(1557.29,-3781.38) ""(1557.3,-3781.38) ""(1557.3,-3781.38) ""(1557.36,-3780.69) ""(1557.36,-3780.69) ""(1557.36,-3780.69) ""(1557.36,-3780.69) ""(1557.53,-3786.9) ""(1557.53,-3786.9) ""(1557.53,-3786.9) ""(1557.53,-3786.9) ""(1557.57,-3782.08) ""(1557.57,-3782.08) ""(1557.57,-3782.08) ""(1557.57,-3782.08) ""(1557.57,-3780) ""(1557.57,-3780) ""(1557.57,-3780) ""(1557.57,-3780) ""(1557.78,-3779.38) ""(1557.78,-3779.38) ""(1557.78,-3779.38) ""(1557.78,-3779.38) ""(1557.92,-3794.82) ""(1557.92,-3794.82) ""(1557.92,-3794.82) ""(1557.92,-3794.82) ""(1557.99,-3782.77) ""(1557.99,-3782.77) ""(1557.99,-3782.77) ""(1557.99,-3782.77) ""(1557.99,-3778.82) ""(1557.99,-3778.82) ""(1557.99,-3778.82) ""(1557.99,-3778.82) ""(1558.44,-3786.12) ""(1558.44,-3786.12) ""(1558.44,-3786.12) ""(1558.44,-3786.12) ""(1558.68,-3778.2) ""(1558.68,-3778.2) ""(1558.68,-3778.2) ""(1558.68,-3778.2) ""(1558.7,-3783.26) ""(1558.7,-3783.26) ""(1558.7,-3783.26) ""(1558.7,-3783.26) ""(1559.35,-3795.86) ""(1559.35,-3795.86) ""(1559.35,-3795.86) ""(1559.35,-3795.86) ""(1559.51,-3777.72) ""(1559.51,-3777.72) ""(1559.51,-3777.72) ""(1559.51,-3777.72) ""(1559.87,-3785.47) ""(1559.87,-3785.47) ""(1559.87,-3785.47) ""(1559.87,-3785.47) ""(1560.2,-3777.3) ""(1560.2,-3777.3) ""(1560.2,-3777.3) ""(1560.2,-3777.3) ""(1561.04,-3777.02) ""(1561.04,-3777.02) ""(1561.04,-3777.02) ""(1561.04,-3777.02) ""(1561.14,-3783.26) ""(1561.14,-3783.26) ""(1561.14,-3783.26) ""(1561.14,-3783.26) ""(1561.17,-3796.77) ""(1561.17,-3796.77) ""(1561.17,-3796.77) ""(1561.17,-3796.77) ""(1561.43,-3784.95) ""(1561.43,-3784.95) ""(1561.43,-3784.95) ""(1561.43,-3784.95) ""(1561.56,-3792.74) ""(1561.56,-3792.74) ""(1561.56,-3792.74) ""(1561.56,-3792.74) ""(1561.69,-3794.3) ""(1561.69,-3794.3) ""(1561.69,-3794.3) ""(1561.69,-3794.3) ""(1561.95,-3791.7) ""(1561.95,-3791.7) ""(1561.95,-3791.7) ""(1561.95,-3791.7) ""(1562.08,-3782.61) ""(1562.08,-3782.61) ""(1562.08,-3782.61) ""(1562.08,-3782.61) ""(1562.21,-3780.79) ""(1562.21,-3780.79) ""(1562.21,-3780.01) ""(1562.21,-3780.01) ""(1562.21,-3780.79) ""(1562.21,-3780.79) ""(1562.21,-3780.01) ""(1562.21,-3780.01) ""(1562.47,-3795.08) ""(1562.47,-3795.08) ""(1562.47,-3795.08) ""(1562.47,-3795.08) ""(1562.47,-3779.75) ""(1562.47,-3779.75) ""(1562.47,-3779.75) ""(1562.47,-3779.75) ""(1562.6,-3781.7) ""(1562.6,-3781.7) ""(1562.6,-3781.7) ""(1562.6,-3781.7) ""(1562.6,-3780.92) ""(1562.6,-3780.92) ""(1562.6,-3780.92) ""(1562.6,-3780.92) ""(1562.99,-3779.23) ""(1562.99,-3779.23) ""(1562.99,-3779.23) ""(1562.99,-3779.23) ""(1563,-3797.28) ""(1563,-3797.28) ""(1563,-3797.28) ""(1563,-3797.28) ""(1563.12,-3790.79) ""(1563.12,-3790.79) ""(1563.12,-3790.79) ""(1563.12,-3790.79) ""(1563.25,-3779.23) ""(1563.25,-3779.23) ""(1563.25,-3779.23) ""(1563.25,-3779.23) ""(1563.51,-3784.17) ""(1563.51,-3784.17) ""(1563.51,-3784.17) ""(1563.51,-3784.17) ""(1563.51,-3776.76) ""(1563.51,-3776.76) ""(1563.51,-3776.76) ""(1563.51,-3776.76) ""(1563.9,-3795.47) ""(1563.9,-3795.47) ""(1563.9,-3795.47) ""(1563.9,-3795.47) ""(1564.03,-3778.97) ""(1564.03,-3778.97) ""(1564.03,-3778.97) ""(1564.03,-3778.97) ""(1564.57,-3797.4) ""(1564.57,-3797.4) ""(1564.57,-3797.4) ""(1564.57,-3797.4) ""(1565.2,-3783.65) ""(1565.2,-3783.65) ""(1565.2,-3783.65) ""(1565.2,-3783.65) ""(1565.2,-3779.23) ""(1565.2,-3779.23) ""(1565.2,-3779.23) ""(1565.2,-3779.23) ""(1565.25,-3797.41) ""(1565.25,-3797.41) ""(1565.25,-3797.41) ""(1565.25,-3797.41) ""(1565.32,-3795.66) ""(1565.32,-3795.66) ""(1565.32,-3795.66) ""(1565.32,-3795.66) ""(1565.33,-3789.88) ""(1565.33,-3789.88) ""(1565.33,-3789.88) ""(1565.33,-3789.88) ""(1565.95,-3797.38) ""(1565.95,-3797.38) ""(1565.95,-3797.38) ""(1565.95,-3797.38) ""(1566.11,-3783.13) ""(1566.11,-3783.13) ""(1566.11,-3783.13) ""(1566.11,-3783.13) ""(1566.11,-3779.36) ""(1566.11,-3779.36) ""(1566.11,-3779.36) ""(1566.11,-3779.36) ""(1566.18,-3795.63) ""(1566.18,-3795.63) ""(1566.63,-3776.76) ""(1566.63,-3776.76) ""(1566.63,-3776.76) ""(1566.63,-3776.76) ""(1566.67,-3795.56) ""(1566.67,-3795.56) ""(1566.67,-3795.56) ""(1566.67,-3795.56) ""(1566.76,-3780.01) ""(1566.76,-3780.01) ""(1566.76,-3780.01) ""(1566.76,-3780.01) ""(1566.87,-3797.33) ""(1566.87,-3797.33) ""(1566.87,-3797.33) ""(1566.87,-3797.33) ""(1566.89,-3782.48) ""(1566.89,-3782.48) ""(1566.89,-3782.48) ""(1566.89,-3782.48) ""(1567.02,-3780.79) ""(1567.02,-3780.79) ""(1567.02,-3780.79) ""(1567.02,-3780.79) ""(1567.05,-3795.45) ""(1567.05,-3795.45) ""(1567.05,-3795.45) ""(1567.05,-3795.45) ""(1567.15,-3781.57) ""(1567.15,-3781.57) ""(1567.15,-3781.57) ""(1567.15,-3781.57) ""(1567.41,-3789.36) ""(1567.41,-3789.36) ""(1567.41,-3789.36) ""(1567.41,-3789.36) ""(1567.69,-3795.25) ""(1567.69,-3795.25) ""(1567.69,-3795.25) ""(1567.69,-3795.25) ""(1567.75,-3793.16) ""(1567.75,-3793.16) ""(1567.75,-3793.16) ""(1567.75,-3793.16) ""(1567.75,-3792.9) ""(1567.75,-3792.9) ""(1567.75,-3792.9) ""(1567.75,-3792.9) ""(1567.77,-3792.53) ""(1567.77,-3792.53) ""(1567.77,-3792.53) ""(1567.77,-3792.53) ""(1567.79,-3793.4) ""(1567.79,-3793.4) ""(1567.79,-3793.4) ""(1567.79,-3793.4) ""(1567.87,-3792.18) ""(1567.87,-3792.18) ""(1567.87,-3792.18) ""(1567.87,-3792.18) ""(1567.93,-3797.29) ""(1567.93,-3797.29) ""(1567.93,-3797.29) ""(1567.93,-3797.29) ""(1568.05,-3794.96) ""(1568.05,-3794.96) ""(1568.05,-3794.96) ""(1568.05,-3794.96) ""(1568.07,-3791.8) ""(1568.07,-3791.8) ""(1568.07,-3791.8) ""(1568.07,-3791.8) ""(1568.14,-3793.85) ""(1568.14,-3793.85) ""(1568.14,-3793.85) ""(1568.14,-3793.85) ""(1568.25,-3794.66) ""(1568.25,-3794.66) ""(1568.25,-3793.98) ""(1568.25,-3793.98) ""(1568.25,-3794.66) ""(1568.25,-3794.66) ""(1568.25,-3793.98) ""(1568.25,-3793.98) ""(1568.32,-3794.23) ""(1568.32,-3794.23) ""(1568.32,-3794.23) ""(1568.32,-3794.23) ""(1568.35,-3791.43) ""(1568.35,-3791.43) ""(1568.35,-3791.43) ""(1568.35,-3791.43) ""(1568.8,-3790.96) ""(1568.8,-3790.96) ""(1568.8,-3790.96) ""(1568.8,-3790.96) ""(1568.84,-3777.41) ""(1568.84,-3777.41) ""(1568.84,-3777.41) ""(1568.84,-3777.41) ""(1569.11,-3797.16) ""(1569.11,-3797.16) ""(1569.11,-3797.16) ""(1569.11,-3797.16) ""(1569.17,-3790.7) ""(1569.17,-3790.7) ""(1569.17,-3790.7) ""(1569.17,-3790.7) ""(1569.37,-3788.33) ""(1569.37,-3788.33) ""(1569.37,-3788.33) ""(1569.37,-3788.33) ""(1569.77,-3790.48) ""(1569.77,-3790.48) ""(1569.77,-3790.48) ""(1569.77,-3790.48) ""(1569.85,-3796.91) ""(1569.85,-3796.91) ""(1569.85,-3796.91) ""(1569.85,-3796.91) ""(1569.89,-3778.32) ""(1569.89,-3778.32) ""(1569.89,-3778.32) ""(1569.89,-3778.32) ""(1570.2,-3790.36) ""(1570.2,-3790.36) ""(1570.2,-3790.36) ""(1570.2,-3790.36) ""(1570.54,-3796.61) ""(1570.54,-3796.61) ""(1570.54,-3796.61) ""(1570.54,-3796.61) ""(1570.74,-3790.36) ""(1570.74,-3790.36) ""(1570.74,-3790.36) ""(1570.74,-3790.36) ""(1571.19,-3787.15) ""(1571.19,-3787.15) ""(1571.19,-3787.15) ""(1571.19,-3787.15) ""(1571.32,-3779.49) ""(1571.32,-3779.49) ""(1571.32,-3779.49) ""(1571.32,-3779.49) ""(1571.37,-3790.43) ""(1571.37,-3790.43) ""(1571.37,-3790.43) ""(1571.37,-3790.43) ""(1571.47,-3796.2) ""(1571.47,-3796.2) ""(1571.47,-3796.2) ""(1571.47,-3796.2) ""(1571.91,-3790.53) ""(1571.91,-3790.53) ""(1571.91,-3790.53) ""(1571.91,-3790.53) ""(1572.1,-3786.51) ""(1572.1,-3786.51) ""(1572.1,-3786.51) ""(1572.1,-3786.51) ""(1572.1,-3780.66) ""(1572.1,-3780.66) ""(1572.1,-3780.66) ""(1572.1,-3780.66) ""(1572.17,-3795.81) ""(1572.17,-3795.81) ""(1572.17,-3795.81) ""(1572.17,-3795.81) ""(1572.34,-3790.8) ""(1572.34,-3790.8) ""(1572.34,-3790.8) ""(1572.34,-3790.8) ""(1572.61,-3795.35) ""(1572.61,-3795.35) ""(1572.61,-3795.35) ""(1572.61,-3795.35) ""(1572.62,-3785.2) ""(1572.62,-3785.2) ""(1572.62,-3785.2) ""(1572.62,-3785.2) ""(1572.62,-3781.96) ""(1572.62,-3781.96) ""(1572.62,-3781.96) ""(1572.62,-3781.96) ""(1572.75,-3783.26) ""(1572.75,-3783.26) ""(1572.75,-3783.26) ""(1572.75,-3783.26) ""(1572.81,-3791.4) ""(1572.81,-3791.4) ""(1572.81,-3791.4) ""(1572.81,-3791.4) ""(1573.09,-3794.8) ""(1573.09,-3794.8) ""(1573.09,-3794.8) ""(1573.09,-3794.8) ""(1573.17,-3792.03) ""(1573.17,-3792.03) ""(1573.17,-3792.03) ""(1573.17,-3792.03) ""(1573.26,-3794.25) ""(1573.26,-3794.25) ""(1573.26,-3794.25) ""(1573.26,-3794.25) ""(1573.41,-3792.65) ""(1573.41,-3792.65) ""(1573.41,-3792.65) ""(1573.41,-3792.65) ""(1576.14,-3786.38) ""(1576.14,-3786.38) ""(1576.14,-3786.38) ""(1576.14,-3786.38) ""(1576.14,-3784.3) ""(1576.14,-3784.3) ""(1576.14,-3784.3) ""(1576.14,-3784.3) ""(1576.4,-3783.13) ""(1576.4,-3783.13) ""(1576.4,-3783.13) ""(1576.4,-3783.13) ""(1576.45,-3793.96) ""(1576.45,-3793.96) ""(1576.45,-3793.96) ""(1576.45,-3793.96) ""(1576.7,-3792.79) ""(1576.7,-3792.79) ""(1576.7,-3792.79) ""(1576.7,-3792.79) ""(1576.91,-3787.15) ""(1576.91,-3787.15) ""(1576.91,-3787.15) ""(1576.91,-3787.15) ""(1577.1,-3792.59) ""(1577.1,-3792.59) ""(1577.1,-3792.59) ""(1577.1,-3792.59) ""(1577.57,-3795.34) ""(1577.57,-3795.34) ""(1577.57,-3795.34) ""(1577.57,-3795.34) ""(1577.7,-3780.79) ""(1577.7,-3780.79) ""(1577.7,-3780.79) ""(1577.7,-3780.79) ""(1577.9,-3795.61) ""(1577.9,-3795.61) ""(1577.9,-3795.61) ""(1577.9,-3795.61) ""(1577.96,-3792.71) ""(1577.96,-3792.71) ""(1577.96,-3792.71) ""(1578.6,-3796.1) ""(1578.6,-3796.1) ""(1578.6,-3796.1) ""(1578.6,-3796.1) ""(1578.87,-3793.52) ""(1578.87,-3793.52) ""(1578.87,-3793.52) ""(1578.87,-3793.52) ""(1579,-3779.23) ""(1579,-3779.23) ""(1579,-3779.23) ""(1579,-3779.23) ""(1579.29,-3796.48) ""(1579.29,-3796.48) ""(1579.29,-3796.48) ""(1579.29,-3796.48) ""(1580,-3794.55) ""(1580,-3794.55) ""(1580,-3794.55) ""(1580,-3794.55) ""(1580.02,-3796.88) ""(1580.02,-3796.88) ""(1580.02,-3796.88) ""(1580.02,-3796.88) ""(1580.17,-3778.06) ""(1580.17,-3778.06) ""(1580.17,-3778.06) ""(1580.17,-3778.06) ""(1580.56,-3794.91) ""(1580.56,-3794.91) ""(1580.56,-3794.91) ""(1580.56,-3794.91) ""(1581.41,-3795.11) ""(1581.41,-3795.11) ""(1581.41,-3795.11) ""(1581.41,-3795.11) ""(1581.47,-3777.28) ""(1581.47,-3777.28) ""(1581.47,-3777.28) ""(1581.47,-3777.28) ""(1581.86,-3797.32) ""(1581.86,-3797.32) ""(1581.86,-3797.32) ""(1581.86,-3797.32) ""(1582.15,-3795.18) ""(1582.15,-3795.18) ""(1582.15,-3795.18) ""(1582.15,-3795.18) ""(1582.25,-3783.91) ""(1582.25,-3783.91) ""(1582.25,-3783.91) ""(1582.25,-3783.91) ""(1582.29,-3784.15) ""(1582.29,-3784.15) ""(1582.29,-3784.15) ""(1582.29,-3784.15) ""(1582.38,-3782.09) ""(1582.38,-3782.09) ""(1582.38,-3782.09) ""(1582.38,-3782.09) ""(1583.05,-3784.82) ""(1583.05,-3784.82) ""(1583.05,-3784.82) ""(1583.05,-3784.82) ""(1583.16,-3780.27) ""(1583.16,-3780.27) ""(1583.16,-3780.27) ""(1583.16,-3780.27) ""(1583.42,-3776.89) ""(1583.42,-3776.89) ""(1583.42,-3776.89) ""(1583.42,-3776.89) ""(1583.94,-3779.49) ""(1583.94,-3779.49) ""(1583.94,-3779.49) ""(1583.94,-3779.49) ""(1583.95,-3795.15) ""(1583.95,-3795.15) ""(1583.95,-3795.15) ""(1583.95,-3795.15) ""(1584.55,-3795.1) ""(1584.55,-3795.1) ""(1584.55,-3795.1) ""(1584.55,-3795.1) ""(1585.05,-3794.93) ""(1585.05,-3794.93) ""(1585.05,-3794.93) ""(1585.05,-3794.93) ""(1585.12,-3779.23) ""(1585.12,-3779.23) ""(1585.12,-3779.23) ""(1585.12,-3779.23) ""(1585.51,-3794.6) ""(1585.51,-3794.6) ""(1585.51,-3794.6) ""(1585.51,-3794.6) ""(1585.64,-3797.42) ""(1585.64,-3797.42) ""(1585.64,-3797.42) ""(1585.64,-3797.42) ""(1586.03,-3776.76) ""(1586.03,-3776.76) ""(1586.03,-3776.76) ""(1586.03,-3776.76) ""(1586.06,-3794.21) ""(1586.06,-3794.21) ""(1586.06,-3794.21) ""(1586.06,-3794.21) ""(1586.29,-3779.23) ""(1586.29,-3779.23) ""(1586.29,-3779.23) ""(1586.29,-3779.23) ""(1586.53,-3793.88) ""(1586.53,-3793.88) ""(1586.53,-3793.88) ""(1586.53,-3793.88) ""(1586.94,-3793.39) ""(1586.94,-3793.39) ""(1586.94,-3793.39) ""(1586.94,-3793.39) ""(1587.33,-3779.75) ""(1587.33,-3779.75) ""(1587.33,-3779.75) ""(1587.33,-3779.75) ""(1587.72,-3797.16) ""(1587.72,-3797.16) ""(1587.72,-3791.96) ""(1587.72,-3791.96) ""(1587.72,-3797.16) ""(1587.72,-3797.16) ""(1587.72,-3791.96) ""(1587.72,-3791.96) ""(1587.88,-3787.15) ""(1587.88,-3787.15) ""(1587.88,-3787.15) ""(1587.88,-3787.15) ""(1587.99,-3784.82) ""(1587.99,-3784.82) ""(1587.99,-3784.82) ""(1587.99,-3784.82) ""(1588.11,-3780.79) ""(1588.11,-3780.79) ""(1588.11,-3777.02) ""(1588.11,-3777.02) ""(1588.11,-3780.79) ""(1588.11,-3780.79) ""(1588.11,-3777.02) ""(1588.11,-3777.02) ""(1588.24,-3790.66) ""(1588.24,-3790.66) ""(1588.24,-3790.66) ""(1588.24,-3790.66) ""(1588.5,-3789.23) ""(1588.5,-3789.23) ""(1588.5,-3789.23) ""(1588.5,-3789.23) ""(1588.5,-3782.22) ""(1588.5,-3782.22) ""(1588.5,-3782.22) ""(1588.5,-3782.22) ""(1588.65,-3788.02) ""(1588.65,-3788.02) ""(1588.65,-3788.02) ""(1588.65,-3788.02) ""(1589.41,-3796.51) ""(1589.41,-3796.51) ""(1589.41,-3796.51) ""(1589.41,-3796.51) ""(1590.06,-3777.54) ""(1590.06,-3777.54) ""(1590.06,-3777.54) ""(1590.06,-3777.54) ""(1591.36,-3778.32) ""(1591.36,-3778.32) ""(1591.36,-3778.32) ""(1591.36,-3778.32) ""(1591.49,-3795.08) ""(1591.49,-3795.08) ""(1591.49,-3795.08) ""(1591.49,-3795.08) ""(1593.18,-3793.78) ""(1593.18,-3793.78) ""(1593.18,-3793.78) ""(1593.18,-3793.78) ""(1593.18,-3780.4) ""(1593.18,-3780.4) ""(1593.18,-3780.4) ""(1593.18,-3780.4) ""(1594.22,-3792.35) ""(1594.22,-3792.35) ""(1594.22,-3792.35) ""(1594.22,-3792.35) ""(1594.35,-3782.09) ""(1594.35,-3782.09) ""(1594.35,-3782.09) ""(1594.35,-3782.09) ""(1595,-3790.01) ""(1595,-3790.01) ""(1595,-3790.01) ""(1595,-3790.01) ""(1595,-3783.39) ""(1595,-3783.39) ""(1595,-3783.39) ""(1595,-3783.39) ""(1595.26,-3786.51) ""(1595.26,-3786.51) ""(1595.26,-3786.51) ""(1595.26,-3786.51) ""(1598.37,-3785.08) ""(1598.37,-3785.08) ""(1598.37,-3785.08) ""(1598.37,-3785.08) ""(1598.5,-3780.92) ""(1598.5,-3780.92) ""(1598.5,-3780.92) ""(1598.5,-3780.92) ""(1598.89,-3778.84) ""(1598.89,-3778.84) ""(1598.89,-3778.84) ""(1598.89,-3778.84) ""(1599.02,-3787.94) ""(1599.02,-3787.94) ""(1599.02,-3787.94) ""(1599.02,-3787.94) ""(1599.54,-3776.76) ""(1599.54,-3776.76) ""(1599.54,-3776.76) ""(1599.54,-3776.76) ""(1600.58,-3790.92) ""(1600.58,-3790.92) ""(1600.58,-3790.92) ""(1600.58,-3790.92) ""(1600.58,-3774.55) ""(1600.58,-3774.55) ""(1600.58,-3774.55) ""(1600.58,-3774.55) ""(1601.88,-3792.48) ""(1601.88,-3792.48) ""(1601.88,-3792.48) ""(1601.88,-3792.48) ""(1602.14,-3772.47) ""(1602.14,-3772.47) ""(1602.14,-3772.47) ""(1602.14,-3772.47) ""(1604.22,-3770.91) ""(1604.22,-3770.91) ""(1604.22,-3770.91) ""(1604.22,-3770.91) ""(1604.35,-3794.56) ""(1604.35,-3794.56) ""(1604.36,-3794.56) ""(1604.36,-3794.56) ""(1605.53,-3781.57) ""(1605.53,-3781.57) ""(1605.53,-3781.57) ""(1605.53,-3781.57) ""(1605.79,-3786.12) ""(1605.79,-3786.12) ""(1605.79,-3786.12) ""(1605.79,-3786.12) ""(1606.05,-3777.28) ""(1606.05,-3777.28) ""(1606.05,-3777.28) ""(1606.05,-3777.28) ""(1606.05,-3769.87) ""(1606.05,-3769.87) ""(1606.05,-3769.87) ""(1606.05,-3769.87) ""(1606.18,-3788.97) ""(1606.18,-3788.97) ""(1606.18,-3788.97) ""(1606.18,-3788.97) ""(1607.09,-3796.12) ""(1607.09,-3796.12) ""(1607.09,-3796.12) ""(1607.09,-3796.12) ""(1607.09,-3791.31) ""(1607.09,-3791.31) ""(1607.09,-3791.31) ""(1607.09,-3791.31) ""(1607.22,-3774.42) ""(1607.22,-3774.42) ""(1607.22,-3774.42) ""(1607.22,-3774.42) ""(1607.22,-3769.48) ""(1607.22,-3769.48) ""(1607.22,-3769.48) ""(1607.22,-3769.48) ""(1608.13,-3792.74) ""(1608.13,-3792.74) ""(1608.13,-3792.74) ""(1608.13,-3792.74) ""(1608.91,-3772.6) ""(1608.91,-3772.6) ""(1608.91,-3772.6) ""(1608.91,-3772.6) ""(1609.17,-3768.96) ""(1609.17,-3768.96) ""(1609.17,-3768.96) ""(1609.17,-3768.96) ""(1609.69,-3793.91) ""(1609.69,-3793.91) ""(1609.69,-3793.91) ""(1609.69,-3793.91) ""(1610.11,-3796.95) ""(1610.11,-3796.95) ""(1610.11,-3796.95) ""(1610.11,-3796.95) ""(1610.32,-3796.97) ""(1610.32,-3796.97) ""(1610.32,-3796.97) ""(1610.32,-3796.97) ""(1610.6,-3771.56) ""(1610.6,-3771.56) ""(1610.6,-3771.56) ""(1610.6,-3771.56) ""(1610.99,-3768.83) ""(1610.99,-3768.83) ""(1610.99,-3768.83) ""(1610.99,-3768.83) ""(1611.51,-3794.82) ""(1611.51,-3794.82) ""(1611.51,-3794.82) ""(1611.51,-3794.82) ""(1611.77,-3771.17) ""(1611.77,-3771.17) ""(1611.77,-3771.17) ""(1611.77,-3771.17) ""(1613.07,-3771.04) ""(1613.07,-3771.04) ""(1613.07,-3771.04) ""(1613.07,-3771.04) ""(1613.2,-3795.08) ""(1613.2,-3795.08) ""(1613.2,-3795.08) ""(1613.2,-3795.08) ""(1615.26,-3770.94) ""(1615.26,-3770.94) ""(1615.26,-3770.94) ""(1615.26,-3770.94) ""(1615.33,-3794.99) ""(1615.33,-3794.99) ""(1615.33,-3794.99) ""(1615.33,-3794.99) ""(1616.06,-3794.22) ""(1616.06,-3794.22) ""(1616.06,-3794.22) ""(1616.06,-3794.22) ""(1616.06,-3771.71) ""(1616.06,-3771.71) ""(1616.06,-3771.71) ""(1616.06,-3771.71) ""(1622.68,-3794.3) ""(1622.68,-3794.3) ""(1622.68,-3794.3) ""(1622.68,-3794.3) ""(1622.68,-3794.17) ""(1622.68,-3793.13) ""(1622.68,-3771.44) ""(1622.68,-3771.44) ""(1622.68,-3771.44) ""(1622.68,-3771.44) ""(1622.68,-3794.17) ""(1622.68,-3793.13) ""(1624.07,-3768.83) ""(1624.07,-3768.83) ""(1624.07,-3768.83) ""(1624.07,-3768.83) ""(1624.11,-3796.97) ""(1624.11,-3796.97) ""(1624.11,-3796.97) ""(1624.11,-3796.97) ""(1625.3,-3796.97) ""(1625.3,-3796.97) ""(1625.3,-3796.97) ""(1625.3,-3796.97) ""(1625.3,-3794.3) ""(1625.3,-3794.3) ""(1625.3,-3794.3) ""(1625.3,-3794.3) ""(1626.32,-3771.44) ""(1626.32,-3771.44) ""(1626.32,-3771.44) ""(1626.32,-3771.44) ""(1626.32,-3768.83) ""(1626.32,-3768.83) ""(1626.32,-3768.83) ""(1626.32,-3768.83)
  round 45 hole 35: ""(1236.55,-3269.23) ""(1236.55,-3090.09) ""(2021,-1106.91) ""(2021.45,-927.78)
  round 60 on Mech2: ""(1351.04,-1973.04)
  round 8.82 on Bottom Overlay: ""(1382.76,-3770.03)
  round 8.65 on Bottom Overlay: ""(1549.35,-3769.76)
